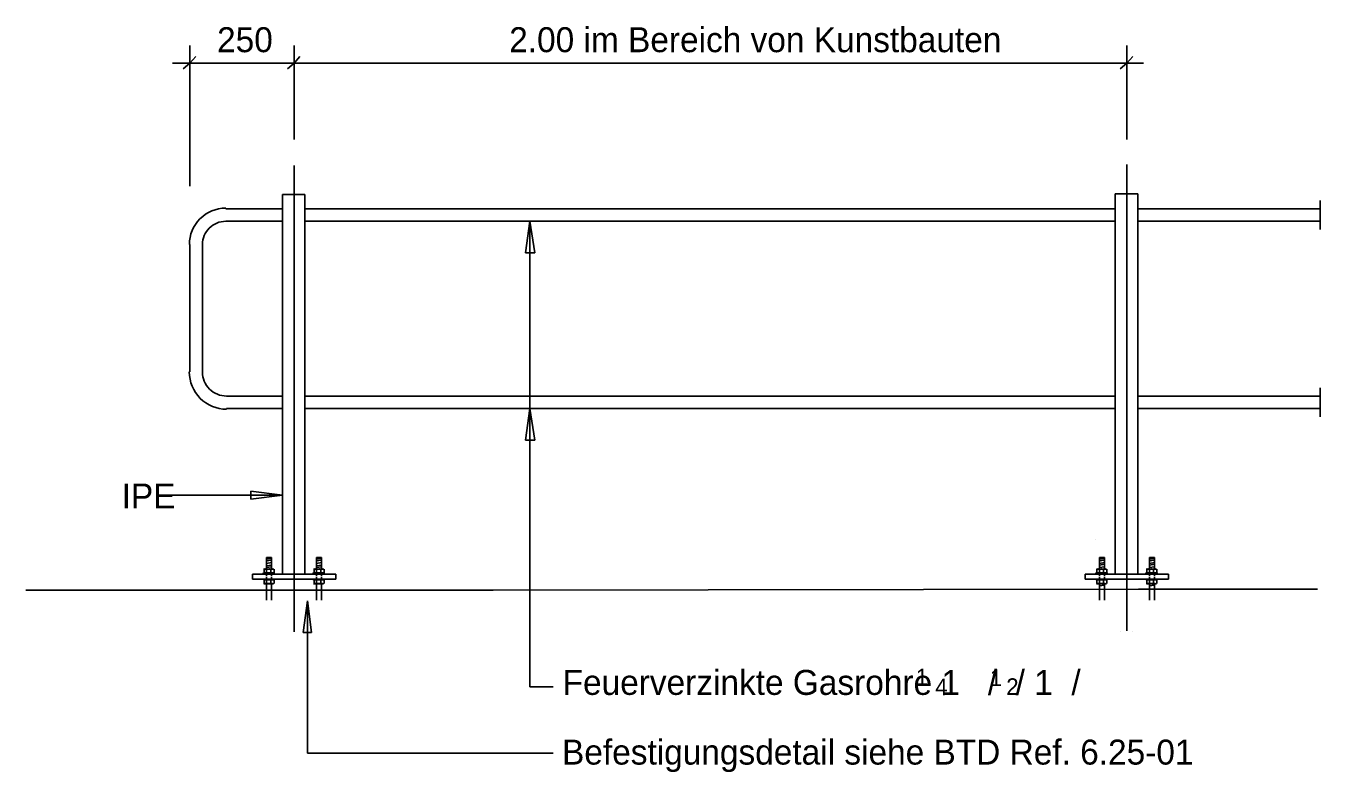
# Model space of a CAD drawing. Extents: x 0.726 to 0.882, y -0.271 to -0.058.
# Drawn here: x 0.7264 to 0.8818, y -0.1473 to -0.0576 of the extents above; entities that cross this region are included whole.
import ezdxf

# ---------------------------------------------------------------- set-up
doc = ezdxf.new("R2010")
doc.units = 0
doc.layers.add('Ebene_02', color=7, linetype='Continuous')

msp = doc.modelspace()

# ---------------------------------------------------------------- linework, layer by layer
at = {"layer": 'Ebene_02'}
for p, q in [((0.7461, -0.07690000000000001), (0.7461, -0.060000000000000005)), ((0.7586, -0.0713), (0.7586, -0.060000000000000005)), ((0.8586, -0.0713), (0.8586, -0.060000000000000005)), ((0.744, -0.0621), (0.8606, -0.0621)), ((0.7461, -0.0621), (0.7453000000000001, -0.06280000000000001)), ((0.7461, -0.0621), (0.7468, -0.0613)), ((0.7586, -0.0621), (0.7578, -0.06280000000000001)), ((0.7586, -0.0621), (0.7593000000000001, -0.0613)), ((0.8586, -0.0621), (0.8578, -0.06280000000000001)), ((0.8586, -0.0621), (0.8593000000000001, -0.0613)), ((0.7586, -0.07440000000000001), (0.7586, -0.13040000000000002)), ((0.8586, -0.0743), (0.8586, -0.1303)), ((0.7572, -0.0779), (0.7599, -0.0779)), ((0.7572, -0.0779), (0.7572, -0.12350000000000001)), ((0.7599, -0.0779), (0.7599, -0.12350000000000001)), ((0.8572000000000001, -0.07780000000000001), (0.8599, -0.07780000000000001)), ((0.8572000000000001, -0.07780000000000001), (0.8572000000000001, -0.12350000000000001)), ((0.8599, -0.07780000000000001), (0.8599, -0.12350000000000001)), ((0.8818, -0.0786), (0.8818, -0.0821)), ((0.7572, -0.0796), (0.7504000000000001, -0.0796)), ((0.8572000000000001, -0.0796), (0.7599, -0.0796)), ((0.8818, -0.0796), (0.8599, -0.0796)), ((0.7572, -0.0811), (0.7504000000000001, -0.0811)), ((0.8572000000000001, -0.0811), (0.7599, -0.0811)), ((0.7864, -0.0849), (0.7869, -0.0811)), ((0.7869, -0.0811), (0.7869, -0.0811)), ((0.7869, -0.0811), (0.7875000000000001, -0.0849)), ((0.7869, -0.0811), (0.7869, -0.137)), ((0.8818, -0.0811), (0.8599, -0.0811)), ((0.7461, -0.0839), (0.7461, -0.09920000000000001)), ((0.7476, -0.0839), (0.7476, -0.09920000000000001)), ((0.7875000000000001, -0.0849), (0.7864, -0.0849)), ((0.7572, -0.10210000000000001), (0.7505000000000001, -0.10210000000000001)), ((0.8572000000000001, -0.10210000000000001), (0.7599, -0.10210000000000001)), ((0.8818, -0.10210000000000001), (0.8599, -0.10210000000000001)), ((0.8818, -0.10110000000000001), (0.8818, -0.1046)), ((0.7572, -0.10360000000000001), (0.7505000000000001, -0.10360000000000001)), ((0.8572000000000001, -0.10360000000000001), (0.7599, -0.10360000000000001)), ((0.7864, -0.10740000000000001), (0.7869, -0.10360000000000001)), ((0.7869, -0.10360000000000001), (0.7869, -0.10360000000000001)), ((0.7869, -0.10360000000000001), (0.7875000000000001, -0.10740000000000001)), ((0.8818, -0.10360000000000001), (0.8599, -0.10360000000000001)), ((0.7875000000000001, -0.10740000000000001), (0.7864, -0.10740000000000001)), ((0.7572, -0.114), (0.743, -0.114)), ((0.7534000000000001, -0.1145), (0.7534000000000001, -0.1135)), ((0.7534000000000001, -0.1135), (0.7572, -0.114)), ((0.7572, -0.114), (0.7534000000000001, -0.1145)), ((0.7572, -0.114), (0.7572, -0.114)), ((0.8548, -0.1193), (0.8548, -0.1193)), ((0.7553000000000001, -0.12150000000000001), (0.7559, -0.12150000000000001)), ((0.7553000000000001, -0.12150000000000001), (0.7553000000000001, -0.12290000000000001)), ((0.7553000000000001, -0.1217), (0.7559, -0.1216)), ((0.7553000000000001, -0.12190000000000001), (0.7559, -0.1218)), ((0.7553000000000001, -0.1222), (0.7559, -0.1221)), ((0.7553000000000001, -0.12250000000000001), (0.7559, -0.12240000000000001)), ((0.7553000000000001, -0.1227), (0.7559, -0.1226)), ((0.7559, -0.12150000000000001), (0.7559, -0.12290000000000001)), ((0.7613000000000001, -0.12150000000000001), (0.7619, -0.12150000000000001)), ((0.7613000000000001, -0.12150000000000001), (0.7613000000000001, -0.12290000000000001)), ((0.7613000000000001, -0.1217), (0.7619, -0.1216)), ((0.7613000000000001, -0.12190000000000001), (0.7619, -0.1218)), ((0.7613000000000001, -0.1222), (0.7619, -0.1221)), ((0.7613000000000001, -0.12250000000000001), (0.7619, -0.12240000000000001)), ((0.7613000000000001, -0.1227), (0.7619, -0.1226)), ((0.7619, -0.12150000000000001), (0.7619, -0.12290000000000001)), ((0.8553000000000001, -0.12150000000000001), (0.8559, -0.12150000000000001)), ((0.8553000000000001, -0.12150000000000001), (0.8553000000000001, -0.12290000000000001)), ((0.8553000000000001, -0.1217), (0.8559, -0.1216)), ((0.8553000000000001, -0.12190000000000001), (0.8559, -0.1218)), ((0.8553000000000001, -0.1222), (0.8559, -0.1221)), ((0.8553000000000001, -0.12240000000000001), (0.8559, -0.1223)), ((0.8553000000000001, -0.1227), (0.8559, -0.1226)), ((0.8559, -0.12150000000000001), (0.8559, -0.12290000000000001)), ((0.8613000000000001, -0.12150000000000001), (0.8619, -0.12150000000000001)), ((0.8613000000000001, -0.12150000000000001), (0.8613000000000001, -0.12290000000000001)), ((0.8613000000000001, -0.1217), (0.8619, -0.1216)), ((0.8613000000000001, -0.12190000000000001), (0.8619, -0.1218)), ((0.8613000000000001, -0.1222), (0.8619, -0.1221)), ((0.8613000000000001, -0.12240000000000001), (0.8619, -0.1223)), ((0.8613000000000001, -0.1227), (0.8619, -0.1226)), ((0.8619, -0.12150000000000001), (0.8619, -0.12290000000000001)), ((0.7536, -0.12350000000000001), (0.7536, -0.1241)), ((0.7636000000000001, -0.12350000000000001), (0.7536, -0.12350000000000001)), ((0.7623000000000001, -0.1241), (0.7536, -0.1241)), ((0.7548, -0.12340000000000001), (0.7548, -0.12350000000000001)), ((0.7548, -0.12340000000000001), (0.7563000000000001, -0.12340000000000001)), ((0.7548, -0.1241), (0.7548, -0.1241)), ((0.7548, -0.1241), (0.7563000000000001, -0.1241)), ((0.755, -0.12290000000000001), (0.755, -0.1233)), ((0.755, -0.1246), (0.755, -0.1242)), ((0.7551, -0.12290000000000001), (0.756, -0.12290000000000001)), ((0.7553000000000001, -0.12290000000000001), (0.7553000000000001, -0.1233)), ((0.7553000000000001, -0.1237), (0.7553000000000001, -0.12350000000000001)), ((0.7553000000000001, -0.124), (0.7553000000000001, -0.12380000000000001)), ((0.7553000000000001, -0.1246), (0.7553000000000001, -0.1242)), ((0.7557, -0.12290000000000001), (0.7559, -0.12290000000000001)), ((0.7558, -0.12290000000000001), (0.7558, -0.1233)), ((0.7558, -0.1246), (0.7558, -0.1242)), ((0.7559, -0.1237), (0.7559, -0.12350000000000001)), ((0.7559, -0.124), (0.7559, -0.12380000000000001)), ((0.7562, -0.12290000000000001), (0.7562, -0.1233)), ((0.7562, -0.1246), (0.7562, -0.1242)), ((0.7563000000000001, -0.12340000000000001), (0.7563000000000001, -0.12350000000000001)), ((0.7563000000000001, -0.1241), (0.7563000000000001, -0.1241)), ((0.7608, -0.12340000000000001), (0.7608, -0.12350000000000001)), ((0.7608, -0.12340000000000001), (0.7623000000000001, -0.12340000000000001)), ((0.7608, -0.1241), (0.7608, -0.1241)), ((0.7608, -0.1241), (0.7623000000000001, -0.1241)), ((0.761, -0.12290000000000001), (0.761, -0.1233)), ((0.761, -0.1246), (0.761, -0.1242)), ((0.7611, -0.12290000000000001), (0.762, -0.12290000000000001)), ((0.7613000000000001, -0.12290000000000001), (0.7613000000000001, -0.1233)), ((0.7613000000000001, -0.1237), (0.7613000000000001, -0.12350000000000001)), ((0.7613000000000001, -0.124), (0.7613000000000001, -0.12380000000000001)), ((0.7613000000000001, -0.1246), (0.7613000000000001, -0.1242)), ((0.7619, -0.12290000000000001), (0.7617, -0.12290000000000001)), ((0.7618, -0.12290000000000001), (0.7618, -0.1233)), ((0.7618, -0.1246), (0.7618, -0.1242)), ((0.7619, -0.1237), (0.7619, -0.12350000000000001)), ((0.7619, -0.124), (0.7619, -0.12380000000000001)), ((0.7622, -0.12290000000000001), (0.7622, -0.1233)), ((0.7622, -0.1246), (0.7622, -0.1242)), ((0.7623000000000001, -0.12340000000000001), (0.7623000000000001, -0.12350000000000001)), ((0.7623000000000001, -0.1241), (0.7623000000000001, -0.1241)), ((0.7623000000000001, -0.1241), (0.7636000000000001, -0.1241)), ((0.7636000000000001, -0.12350000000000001), (0.7636000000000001, -0.1241)), ((0.8536, -0.12350000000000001), (0.8536, -0.1241)), ((0.8636, -0.12350000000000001), (0.8536, -0.12350000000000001)), ((0.8623000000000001, -0.1241), (0.8536, -0.1241)), ((0.8548, -0.12340000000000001), (0.8548, -0.12350000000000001)), ((0.8548, -0.12340000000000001), (0.8563000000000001, -0.12340000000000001)), ((0.8548, -0.1241), (0.8548, -0.1241)), ((0.8548, -0.1241), (0.8563000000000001, -0.1241)), ((0.8550000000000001, -0.12290000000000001), (0.8550000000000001, -0.1233)), ((0.8550000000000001, -0.1246), (0.8550000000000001, -0.1242)), ((0.8551000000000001, -0.12290000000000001), (0.8560000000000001, -0.12290000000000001)), ((0.8553000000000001, -0.12290000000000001), (0.8553000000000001, -0.1233)), ((0.8553000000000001, -0.1237), (0.8553000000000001, -0.12350000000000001)), ((0.8553000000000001, -0.124), (0.8553000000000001, -0.12380000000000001)), ((0.8553000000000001, -0.1246), (0.8553000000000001, -0.1242)), ((0.8557, -0.12290000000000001), (0.8559, -0.12290000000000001)), ((0.8558, -0.12290000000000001), (0.8558, -0.1233)), ((0.8558, -0.1246), (0.8558, -0.1242)), ((0.8559, -0.1237), (0.8559, -0.12350000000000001)), ((0.8559, -0.124), (0.8559, -0.12380000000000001)), ((0.8562000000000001, -0.12290000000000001), (0.8562000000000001, -0.1233)), ((0.8562000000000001, -0.1246), (0.8562000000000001, -0.1242)), ((0.8563000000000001, -0.12340000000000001), (0.8563000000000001, -0.12350000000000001)), ((0.8563000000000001, -0.1241), (0.8563000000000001, -0.1241)), ((0.8608, -0.12340000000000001), (0.8608, -0.12350000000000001)), ((0.8608, -0.12340000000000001), (0.8623000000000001, -0.12340000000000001)), ((0.8608, -0.1241), (0.8608, -0.1241)), ((0.8608, -0.1241), (0.8623000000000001, -0.1241)), ((0.861, -0.12290000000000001), (0.861, -0.1233)), ((0.861, -0.1246), (0.861, -0.1242)), ((0.8611000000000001, -0.12290000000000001), (0.862, -0.12290000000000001)), ((0.8613000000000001, -0.12290000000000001), (0.8613000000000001, -0.1233)), ((0.8613000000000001, -0.1237), (0.8613000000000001, -0.12350000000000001)), ((0.8613000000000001, -0.124), (0.8613000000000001, -0.12380000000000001)), ((0.8613000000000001, -0.1246), (0.8613000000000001, -0.1242)), ((0.8619, -0.12290000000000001), (0.8617, -0.12290000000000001)), ((0.8618, -0.12290000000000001), (0.8618, -0.1233)), ((0.8618, -0.1246), (0.8618, -0.1242)), ((0.8619, -0.1237), (0.8619, -0.12350000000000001)), ((0.8619, -0.124), (0.8619, -0.12380000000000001)), ((0.8622000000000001, -0.12290000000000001), (0.8622000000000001, -0.1233)), ((0.8622000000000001, -0.1246), (0.8622000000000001, -0.1242)), ((0.8623000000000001, -0.12340000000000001), (0.8623000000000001, -0.12350000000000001)), ((0.8623000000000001, -0.1241), (0.8623000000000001, -0.1241)), ((0.8623000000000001, -0.1241), (0.8636, -0.1241)), ((0.8636, -0.12350000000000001), (0.8636, -0.1241)), ((0.7264, -0.1254), (0.7825000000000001, -0.1254)), ((0.7551, -0.1246), (0.756, -0.1246)), ((0.7553000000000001, -0.12480000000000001), (0.7553000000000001, -0.1246)), ((0.7553000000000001, -0.12480000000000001), (0.7553000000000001, -0.12660000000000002)), ((0.7559, -0.12480000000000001), (0.7559, -0.1246)), ((0.7559, -0.12480000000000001), (0.7559, -0.12660000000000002)), ((0.7611, -0.1246), (0.762, -0.1246)), ((0.7613000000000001, -0.1246), (0.7613000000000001, -0.12480000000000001)), ((0.7613000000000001, -0.12480000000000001), (0.7613000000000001, -0.12660000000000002)), ((0.7619, -0.1246), (0.7619, -0.12480000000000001)), ((0.7619, -0.12480000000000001), (0.7619, -0.12660000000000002)), ((0.7825000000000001, -0.1254), (0.86, -0.1253)), ((0.8551000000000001, -0.1246), (0.8560000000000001, -0.1246)), ((0.8553000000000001, -0.1247), (0.8557, -0.1246)), ((0.8553000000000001, -0.12480000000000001), (0.8553000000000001, -0.1246)), ((0.8553000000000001, -0.12480000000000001), (0.8553000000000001, -0.12660000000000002)), ((0.8553000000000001, -0.12490000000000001), (0.8559, -0.12480000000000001)), ((0.8559, -0.12480000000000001), (0.8559, -0.1246)), ((0.8559, -0.12480000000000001), (0.8559, -0.12660000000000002)), ((0.86, -0.1253), (0.8815000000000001, -0.1253)), ((0.8611000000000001, -0.1246), (0.862, -0.1246)), ((0.8613000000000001, -0.1247), (0.8617, -0.1246)), ((0.8613000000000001, -0.1246), (0.8613000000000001, -0.12480000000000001)), ((0.8613000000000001, -0.12480000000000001), (0.8613000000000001, -0.12660000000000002)), ((0.8613000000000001, -0.12490000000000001), (0.8619, -0.12480000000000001)), ((0.8619, -0.1246), (0.8619, -0.12480000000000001)), ((0.8619, -0.12480000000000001), (0.8619, -0.12660000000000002)), ((0.7597, -0.1305), (0.7602, -0.1267)), ((0.7602, -0.1267), (0.7607, -0.1305)), ((0.7602, -0.14500000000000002), (0.7602, -0.1267)), ((0.7607, -0.1305), (0.7597, -0.1305)), ((0.8578, -0.13040000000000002), (0.8578, -0.13040000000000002)), ((0.8593000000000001, -0.13040000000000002), (0.8593000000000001, -0.13040000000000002)), ((0.7869, -0.137), (0.7897000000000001, -0.137)), ((0.7602, -0.14500000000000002), (0.7897000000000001, -0.14500000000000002))]:
    msp.add_line(p, q, dxfattribs=at)
for points in [[(0.787, -0.08120000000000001), (0.787, -0.08120000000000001)], [(0.787, -0.1037), (0.787, -0.1037)], [(0.7571, -0.114), (0.7571, -0.114)]]:
    msp.add_lwpolyline(points, close=True, dxfattribs=at)
for centre, radius, start, end in [((0.7504000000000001, -0.0839), 0.004373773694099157, 90.01698055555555, 180.0339611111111), ((0.7504000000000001, -0.0839), 0.002793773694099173, 90.01698055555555, 180.0339611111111), ((0.7505000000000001, -0.09920000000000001), 0.00448152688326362, 180.0339638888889, 270.05094444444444), ((0.7505000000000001, -0.09920000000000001), 0.0029015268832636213, 180.0339638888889, 270.05094444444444)]:
    msp.add_arc(centre, radius, start, end, dxfattribs=at)
for centre, major_axis, ratio, start_param, end_param in [((0.7551, -0.12290000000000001), (-0.00016621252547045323, 2.0355163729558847e-20), 0.22718841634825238, 3.084898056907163, 6.341657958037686), ((0.7551, -0.1242), (-0.00016621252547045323, 2.0355163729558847e-20), 0.22718841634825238, 3.084898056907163, 6.341657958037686), ((0.7551, -0.1233), (-0.00016621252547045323, 2.0355163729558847e-20), 0.22718841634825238, 6.227083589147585, 9.483843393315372), ((0.7556, -0.12290000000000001), (-0.00026864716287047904, 3.2899788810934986e-20), 0.14136656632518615, 3.0795212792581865, 6.347034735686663), ((0.7556, -0.1242), (-0.00026864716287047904, 3.2899788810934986e-20), 0.14136656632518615, 3.0795212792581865, 6.347034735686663), ((0.7556, -0.1233), (-0.00026864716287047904, 3.2899788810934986e-20), 0.14136656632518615, 6.221706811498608, 9.48922017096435), ((0.756, -0.12290000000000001), (0.00016621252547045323, 0), 0.22718841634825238, 6.227083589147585, 9.483843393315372), ((0.756, -0.1242), (0.00016621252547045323, 0), 0.22718841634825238, 6.227083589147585, 9.483843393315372), ((0.756, -0.1233), (0.00016621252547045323, 0), 0.22718841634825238, 3.084898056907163, 6.341657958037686), ((0.7611, -0.12290000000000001), (-0.00016621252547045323, 2.0355163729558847e-20), 0.22718841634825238, 3.084898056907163, 6.341657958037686), ((0.7611, -0.1242), (-0.00016621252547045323, 2.0355163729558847e-20), 0.22718841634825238, 3.084898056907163, 6.341657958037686), ((0.7611, -0.1233), (-0.00016621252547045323, 2.0355163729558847e-20), 0.22718841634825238, 6.227083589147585, 9.483843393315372), ((0.7616, -0.12290000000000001), (-0.00026864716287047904, 3.2899788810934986e-20), 0.14136656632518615, 3.0795212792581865, 6.347034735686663), ((0.7616, -0.1242), (-0.00026864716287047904, 3.2899788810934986e-20), 0.14136656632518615, 3.0795212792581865, 6.347034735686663), ((0.7616, -0.1233), (-0.00026864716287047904, 3.2899788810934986e-20), 0.14136656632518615, 6.221706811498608, 9.48922017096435), ((0.762, -0.12290000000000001), (0.00016621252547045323, 0), 0.22718841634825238, 6.227083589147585, 9.483843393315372), ((0.762, -0.1242), (0.00016621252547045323, 0), 0.22718841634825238, 6.227083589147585, 9.483843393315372), ((0.762, -0.1233), (0.00016621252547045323, 0), 0.22718841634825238, 3.084898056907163, 6.341657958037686), ((0.8551000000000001, -0.12290000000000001), (-0.00016621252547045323, 2.0355163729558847e-20), 0.22718841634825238, 3.084898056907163, 6.341657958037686), ((0.8551000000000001, -0.1242), (-0.00016621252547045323, 2.0355163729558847e-20), 0.22718841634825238, 3.084898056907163, 6.341657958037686), ((0.8551000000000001, -0.1233), (-0.00016621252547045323, 2.0355163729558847e-20), 0.22718841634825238, 6.227083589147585, 9.483843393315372), ((0.8556, -0.12290000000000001), (-0.00026864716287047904, 3.2899788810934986e-20), 0.14136656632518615, 3.0795212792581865, 6.347034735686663), ((0.8556, -0.1242), (-0.00026864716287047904, 3.2899788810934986e-20), 0.14136656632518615, 3.0795212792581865, 6.347034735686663), ((0.8556, -0.1233), (-0.00026864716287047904, 3.2899788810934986e-20), 0.14136656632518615, 6.221706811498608, 9.48922017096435), ((0.8560000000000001, -0.12290000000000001), (0.00016621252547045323, 0), 0.22718841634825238, 6.227083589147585, 9.483843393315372), ((0.8560000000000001, -0.1242), (0.00016621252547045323, 0), 0.22718841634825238, 6.227083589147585, 9.483843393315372), ((0.8560000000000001, -0.1233), (0.00016621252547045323, 0), 0.22718841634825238, 3.084898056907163, 6.341657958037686), ((0.8611000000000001, -0.12290000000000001), (-0.00016621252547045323, 2.0355163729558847e-20), 0.22718841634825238, 3.084898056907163, 6.341657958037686), ((0.8611000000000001, -0.1242), (-0.00016621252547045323, 2.0355163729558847e-20), 0.22718841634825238, 3.084898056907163, 6.341657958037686), ((0.8611000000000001, -0.1233), (-0.00016621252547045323, 2.0355163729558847e-20), 0.22718841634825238, 6.227083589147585, 9.483843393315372), ((0.8616, -0.12290000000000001), (-0.00026864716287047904, 3.2899788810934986e-20), 0.14136656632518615, 3.0795212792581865, 6.347034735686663), ((0.8616, -0.1242), (-0.00026864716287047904, 3.2899788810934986e-20), 0.14136656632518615, 3.0795212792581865, 6.347034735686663), ((0.8616, -0.1233), (-0.00026864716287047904, 3.2899788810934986e-20), 0.14136656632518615, 6.221706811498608, 9.48922017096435), ((0.862, -0.12290000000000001), (0.00016621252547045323, 0), 0.22718841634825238, 6.227083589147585, 9.483843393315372), ((0.862, -0.1242), (0.00016621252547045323, 0), 0.22718841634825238, 6.227083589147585, 9.483843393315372), ((0.862, -0.1233), (0.00016621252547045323, 0), 0.22718841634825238, 3.084898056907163, 6.341657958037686), ((0.7551, -0.1246), (-0.00016621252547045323, 2.0355163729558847e-20), 0.22718841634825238, 6.227083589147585, 9.483843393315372), ((0.7556, -0.1246), (-0.00026864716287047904, 3.2899788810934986e-20), 0.14136656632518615, 6.221706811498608, 9.48922017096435), ((0.756, -0.1246), (0.00016621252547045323, 0), 0.22718841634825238, 3.084898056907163, 6.341657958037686), ((0.7611, -0.1246), (-0.00016621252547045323, 2.0355163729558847e-20), 0.22718841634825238, 6.227083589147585, 9.483843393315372), ((0.7616, -0.1246), (-0.00026864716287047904, 3.2899788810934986e-20), 0.14136656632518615, 6.221706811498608, 9.48922017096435), ((0.762, -0.1246), (0.00016621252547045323, 0), 0.22718841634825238, 3.084898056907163, 6.341657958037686), ((0.8551000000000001, -0.1246), (-0.00016621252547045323, 2.0355163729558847e-20), 0.22718841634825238, 6.227083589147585, 9.483843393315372), ((0.8556, -0.1246), (-0.00026864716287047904, 3.2899788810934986e-20), 0.14136656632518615, 6.221706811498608, 9.48922017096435), ((0.8560000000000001, -0.1246), (0.00016621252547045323, 0), 0.22718841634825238, 3.084898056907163, 6.341657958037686), ((0.8611000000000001, -0.1246), (-0.00016621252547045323, 2.0355163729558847e-20), 0.22718841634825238, 6.227083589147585, 9.483843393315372), ((0.8616, -0.1246), (-0.00026864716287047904, 3.2899788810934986e-20), 0.14136656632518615, 6.221706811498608, 9.48922017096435), ((0.862, -0.1246), (0.00016621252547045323, 0), 0.22718841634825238, 3.084898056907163, 6.341657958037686)]:
    msp.add_ellipse(centre, major_axis=major_axis, ratio=ratio, start_param=start_param, end_param=end_param, dxfattribs=at)

# ---------------------------------------------------------------- texts
for s, height, p in [('250', 0.003, (0.7493564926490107, -0.0608)), ('2.00 im Bereich von Kunstbauten', 0.003, (0.7844321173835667, -0.0608)), ('IPE', 0.003, (0.7379, -0.1156001)), ('Feuerverzinkte Gasrohre 1   /  / 1  /', 0.003, (0.7908444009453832, -0.13798776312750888)), ('1', 0.002, (0.8332608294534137, -0.13683431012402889)), ('1', 0.002, (0.8421382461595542, -0.13693398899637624)), ('4', 0.002, (0.8355751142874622, -0.13802802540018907)), ('2', 0.002, (0.8441108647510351, -0.1379957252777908)), ('Befestigungsdetail siehe BTD Ref. 6.25-01', 0.003, (0.7907752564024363, -0.14635653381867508))]:
    msp.add_text(s, height=height, dxfattribs=at).set_placement(p)

doc.saveas('drawing.dxf')
